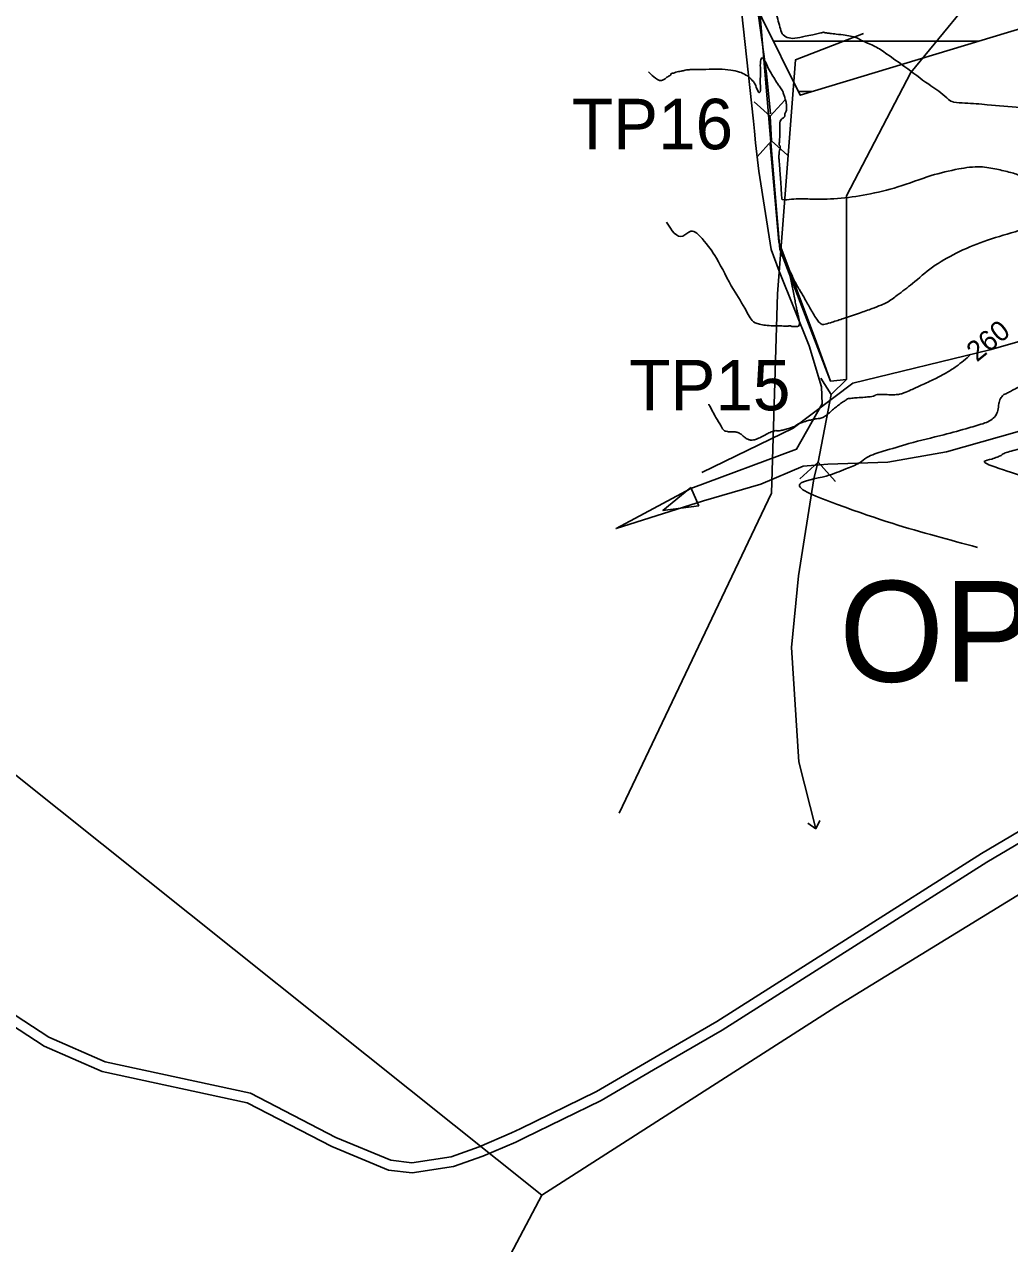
# Model space of a CAD drawing. Extents: x -478232 to -472707, y -1118753 to -1113967.
# Drawn here: x -476364.6 to -476169.2, y -1115916.9 to -1115675.1 of the extents above; entities that cross this region are included whole.
import ezdxf

# ---------------------------------------------------------------- set-up
doc = ezdxf.new("R2010")
doc.units = 0
for name, color, linetype in [('cesty', 7, 'Continuous'), ('DESQ_pomoc', 7, 'Continuous'), ('el vedeni _VN', 7, 'Continuous'), ('meliorace', 7, 'Continuous'), ('ObPÚ', 7, 'Continuous'), ('plyn_stl', 7, 'Continuous'), ('příkop', 7, 'Continuous'), ('silnice', 7, 'Continuous'), ('TP _navrh', 7, 'Continuous'), ('TP_stavajicí_mosty', 7, 'Continuous'), ('vodní plochy', 7, 'Continuous'), ('Vrstevnice_hlavni', 7, 'Continuous'), ('Vrstevnice_popis', 7, 'Continuous'), ('Vrstevnice_vedlejsi', 7, 'Continuous')]:
    doc.layers.add(name, color=color, linetype=linetype)

msp = doc.modelspace()

# ---------------------------------------------------------------- linework, layer by layer
at = {"layer": 'cesty'}
msp.add_line((-476230.782, -1115770.594), (-476232.376, -1115766.926), dxfattribs=at)
msp.add_lwpolyline([(-476232.376, -1115766.926), (-476237.951, -1115771.528), (-476230.782, -1115770.594)], dxfattribs=at)
at = {"layer": 'DESQ_pomoc'}
for points in [[(-476201.534, -1115745.526), (-476201.534, -1115733.375), (-476201.534, -1115709.114), (-476188.744, -1115684.672), (-476172.449, -1115664.757), (-476160.138, -1115645.565), (-476134.066, -1115608.631), (-476115.78, -1115589.982), (-476098.037, -1115567.894), (-476077.94, -1115547.978), (-476048.248, -1115512.854), (-476043.993, -1115447.585)], [(-476267.087, -1115462.209), (-476244.37, -1115506.43), (-476242.315, -1115514.072), (-476242.274, -1115519.975), (-476242.646, -1115529.053), (-476245.764, -1115545.902), (-476246.268, -1115555.752), (-476245.646, -1115566.754), (-476228.592, -1115621.781), (-476225.387, -1115633.24), (-476218.708, -1115672.632), (-476214.725, -1115719.706), (-476204.67, -1115745.863), (-476201.534, -1115745.526)]]:
    msp.add_lwpolyline(points, dxfattribs=at)
at = {"layer": 'el vedeni _VN'}
msp.add_lwpolyline([(-476246.598, -1115831.504), (-476216.386, -1115768.05), (-476215.19, -1115728.562), (-476211.67, -1115682.14), (-476198.145, -1115676.925)], dxfattribs=at)
at = {"layer": 'meliorace'}
for p, q in [((-476216.019, -1115678.417), (-476175.305, -1115678.417)), ((-476211.058, -1115688.417), (-476208.305, -1115688.417))]:
    msp.add_line(p, q, dxfattribs=at)
msp.add_lwpolyline([(-475930.536, -1115473.639), (-475966.096, -1115498.642), (-475977.78, -1115575.318), (-475994.29, -1115626.039), (-476095.89, -1115666.758), (-476110.114, -1115658.662), (-476210.698, -1115689.142), (-476225.938, -1115658.424), (-476218.572, -1115651.28), (-476221.366, -1115635.564), (-476230.256, -1115618.895), (-476240.416, -1115599.845), (-476255.656, -1115572.46), (-476259.466, -1115568.889), (-476264.546, -1115546.267), (-476300.106, -1115567.698), (-476326.776, -1115514.12)], dxfattribs=at)
at = {"layer": 'ObPÚ'}
msp.add_lwpolyline([(-476225.42, -1115644.37), (-476219.95, -1115694.26), (-476219.77, -1115696.28), (-476219.56, -1115698.57), (-476218.93, -1115704.24), (-476216.46, -1115719.75), (-476214.88, -1115724.06), (-476208.91, -1115738.82), (-476206.48, -1115747), (-476206.37, -1115750.33), (-476211.42, -1115759.32), (-476232.43, -1115767.11), (-476247.23, -1115775.1), (-476229.89, -1115769.61), (-476218.53, -1115766.28), (-476210.09, -1115762.68), (-476205.25, -1115762.34), (-476193.32, -1115761.9), (-476181.71, -1115759.89), (-476167.64, -1115755.89), (-476126.07, -1115741.56), (-476097.4, -1115735.87), (-476082.36, -1115734.08), (-476080.7, -1115733.86)], dxfattribs=at)
at = {"layer": 'plyn_stl'}
msp.add_lwpolyline([(-476230.25, -1115763.97), (-476212.09, -1115755.18), (-476200.29, -1115746.23), (-476173.09, -1115739.64), (-476150.98, -1115733.39)], dxfattribs=at)
at = {"layer": 'příkop'}
for q in [(-476209.19, -1115833.49), (-476206.807, -1115832.957)]:
    msp.add_line((-476207.63, -1115834.61), q, dxfattribs=at)
for points in [[(-476224.857, -1115633.023), (-476224.505, -1115634.082), (-476223.006, -1115644.102), (-476219.219, -1115671.509), (-476217.407, -1115684.861), (-476216.585, -1115692.813)], [(-476216.661, -1115698.872), (-476214.95, -1115718.2), (-476207.45, -1115738.16), (-476204.67, -1115745.863)], [(-476207.11, -1115761.74), (-476207.99, -1115765.23), (-476211.04, -1115784.48), (-476212.45, -1115798.65), (-476210.97, -1115821.36), (-476207.63, -1115834.61)]]:
    msp.add_lwpolyline(points, dxfattribs=at)
at = {"layer": 'silnice'}
for points in [[(-476261.922, -1115907.288), (-476203.622, -1115869.922), (-476022.083, -1115758.582), (-475811.314, -1115629.283), (-475771.826, -1115610.299), (-475706.185, -1115581.566), (-475629.775, -1115551.807), (-475577.467, -1115527.178), (-475544.647, -1115503.063), (-475523.184, -1115471.236), (-475482.102, -1115402.498), (-475367.21, -1115204.445), (-475326.334, -1115129.255), (-475275.418, -1115058.05)], [(-475903.982, -1117378.322), (-475889.519, -1117318.176), (-475888.389, -1117289.008), (-475895.395, -1117261.196), (-475916.638, -1117209.19), (-475969.886, -1117075.455), (-476021.05, -1116948.737), (-476052.923, -1116863.979), (-476081.44, -1116727.192), (-476114.99, -1116491.378), (-476128.411, -1116405.781), (-476137.637, -1116368.017), (-476162.8, -1116322.7), (-476200.543, -1116268.153), (-476239.965, -1116179.199), (-476260.934, -1116109.546), (-476288.613, -1116007.164), (-476289.451, -1115970.24), (-476274.354, -1115930.798), (-476261.922, -1115907.288), (-476366.595, -1115823.727)]]:
    msp.add_lwpolyline(points, dxfattribs=at)
at = {"layer": 'TP _navrh'}
msp.add_lwpolyline([(-476206.636, -1115745.227), (-476204.533, -1115748.511), (-476201.534, -1115745.526), (-476204.533, -1115748.511), (-476207.14, -1115761.941), (-476203.773, -1115765.701), (-476207.14, -1115761.941), (-476210.802, -1115765.219)], dxfattribs=at)
at = {"layer": 'TP_stavajicí_mosty'}
for p, q in [((-476219.849, -1115690.463), (-476216.667, -1115693.304)), ((-476213.769, -1115690.14), (-476216.633, -1115693.302)), ((-476216.667, -1115693.304), (-476216.388, -1115698.181)), ((-476216.633, -1115693.302), (-476216.394, -1115698.181)), ((-476216.388, -1115698.181), (-476219.225, -1115701.366)), ((-476216.394, -1115698.181), (-476213.236, -1115701.048))]:
    msp.add_line(p, q, dxfattribs=at)
at = {"layer": 'vodní plochy'}
for points in [[(-475779.213, -1115723.58), (-475781.955, -1115723.615), (-475790.416, -1115718.325), (-475794.426, -1115716.682), (-475798.584, -1115714.694), (-475810.721, -1115710.345), (-475841.882, -1115701.514), (-475880.38, -1115690.714), (-475893.822, -1115686.598), (-475898.085, -1115684.655), (-475904.925, -1115681.219), (-475916.412, -1115686.876), (-475958.026, -1115710.973), (-475986.66, -1115727.189), (-476011.342, -1115743.218), (-476037.238, -1115758.87), (-476062.612, -1115773.996), (-476091.04, -1115791.638), (-476123.208, -1115810.698), (-476141.742, -1115820.058), (-476174.712, -1115839.526), (-476227.25, -1115872.829), (-476240.81, -1115880.736)], [(-476265.408, -1115895.911), (-476250.185, -1115888.516), (-476239.802, -1115882.464), (-476226.21, -1115874.539), (-476173.668, -1115841.232), (-476140.782, -1115821.814), (-476122.246, -1115812.452), (-476090.002, -1115793.348), (-476061.572, -1115775.704), (-476036.208, -1115760.584), (-476010.28, -1115744.912), (-475985.622, -1115728.899)], [(-476375.634, -1115868.031), (-476360.7, -1115877.712), (-476349.186, -1115882.767), (-476320.432, -1115888.987), (-476303.631, -1115897.664), (-476292.397, -1115902.299), (-476287.698, -1115902.886), (-476279.459, -1115901.618), (-476273.652, -1115899.541), (-476267.142, -1115896.753), (-476265.408, -1115895.911)], [(-476240.81, -1115880.736), (-476251.127, -1115886.75), (-476266.282, -1115894.111), (-476267.974, -1115894.933), (-476274.384, -1115897.679), (-476279.953, -1115899.67), (-476287.726, -1115900.866), (-476291.883, -1115900.347), (-476302.789, -1115895.848), (-476319.75, -1115887.089), (-476348.566, -1115880.855), (-476359.748, -1115875.946), (-476374.7, -1115866.253)]]:
    msp.add_lwpolyline(points, dxfattribs=at)
at = {"layer": 'Vrstevnice_hlavni'}
msp.add_spline([(-476176.894, -1115740.594), (-476179.767, -1115742.933), (-476181.643, -1115744.14), (-476183.957, -1115745.384), (-476186.71, -1115746.665), (-476188.764, -1115747.593), (-476190.119, -1115748.168), (-476190.776, -1115748.389), (-476191.667, -1115748.519), (-476192.794, -1115748.555), (-476194.156, -1115748.499), (-476195.11, -1115748.495), (-476195.655, -1115748.543), (-476195.793, -1115748.644), (-476195.934, -1115748.73), (-476196.079, -1115748.799), (-476196.227, -1115748.853), (-476196.83, -1115748.929), (-476197.887, -1115749.028), (-476199.398, -1115749.15), (-476200.445, -1115749.235), (-476201.027, -1115749.285), (-476201.146, -1115749.299), (-476201.498, -1115749.498), (-476202.086, -1115749.883), (-476202.907, -1115750.454), (-476203.72, -1115751.074), (-476204.524, -1115751.744), (-476205.32, -1115752.464), (-476206.072, -1115752.964), (-476206.783, -1115753.244), (-476207.45, -1115753.304), (-476208.234, -1115753.449), (-476209.135, -1115753.679), (-476210.153, -1115753.993), (-476210.906, -1115754.266), (-476211.393, -1115754.497), (-476211.614, -1115754.688), (-476212.08, -1115754.912), (-476212.79, -1115755.169), (-476213.745, -1115755.459), (-476214.525, -1115755.637), (-476215.131, -1115755.704), (-476215.563, -1115755.658), (-476216.23, -1115755.836), (-476217.132, -1115756.235), (-476218.27, -1115756.858), (-476219.217, -1115757.28), (-476219.972, -1115757.503), (-476220.536, -1115757.525), (-476221.11, -1115757.362), (-476221.694, -1115757.012), (-476222.288, -1115756.476), (-476222.921, -1115756.117), (-476223.595, -1115755.935), (-476224.308, -1115755.93), (-476224.899, -1115755.886), (-476225.368, -1115755.803), (-476225.715, -1115755.681), (-476226.397, -1115754.772), (-476227.416, -1115753.074), (-476228.77, -1115750.587), (-476228.855, -1115750.439)], degree=3, dxfattribs=at)
at = {"layer": 'Vrstevnice_vedlejsi'}
for points in [[(-476227.986, -1115661.616), (-476227.829, -1115661.539), (-476227.091, -1115661.275), (-476225.773, -1115660.825), (-476223.875, -1115660.188), (-476222.549, -1115659.504), (-476221.794, -1115658.774), (-476221.612, -1115657.996), (-476221.483, -1115656.864), (-476221.409, -1115655.377), (-476221.39, -1115653.536), (-476221.219, -1115653), (-476220.898, -1115653.77), (-476220.425, -1115655.846), (-476220.044, -1115657.446), (-476219.755, -1115658.57), (-476219.557, -1115659.218), (-476219.119, -1115660.554), (-476218.442, -1115662.578), (-476217.526, -1115665.29), (-476216.754, -1115667.802), (-476216.127, -1115670.113), (-476215.643, -1115672.223), (-476215.172, -1115674.064), (-476214.714, -1115675.636), (-476214.269, -1115676.94), (-476213.291, -1115677.677), (-476211.778, -1115677.849), (-476209.732, -1115677.456), (-476208.193, -1115677.148), (-476207.162, -1115676.926), (-476206.639, -1115676.791), (-476206.278, -1115676.698), (-476206.079, -1115676.648), (-476206.043, -1115676.641), (-476205.991, -1115676.654), (-476205.924, -1115676.688), (-476205.841, -1115676.743), (-476205.736, -1115676.78), (-476205.61, -1115676.801), (-476205.463, -1115676.803), (-476204.774, -1115676.881), (-476203.544, -1115677.033), (-476201.772, -1115677.26), (-476200.409, -1115677.509), (-476199.454, -1115677.779), (-476198.909, -1115678.071), (-476198.137, -1115678.448), (-476197.139, -1115678.909), (-476195.914, -1115679.454), (-476193.519, -1115680.981), (-476189.955, -1115683.489), (-476185.22, -1115686.977), (-476182.029, -1115689.311), (-476180.382, -1115690.49), (-476180.278, -1115690.514), (-476178.021, -1115690.699), (-476173.61, -1115691.044), (-476167.046, -1115691.55), (-476162.398, -1115691.805), (-476159.667, -1115691.807), (-476158.853, -1115691.558), (-476157.344, -1115691.399), (-476155.139, -1115691.33), (-476152.239, -1115691.352), (-476149.334, -1115691.272), (-476146.424, -1115691.091), (-476143.508, -1115690.808), (-476141.245, -1115690.475), (-476139.633, -1115690.092), (-476138.674, -1115689.658), (-476137.503, -1115688.952), (-476136.121, -1115687.974), (-476134.526, -1115686.724), (-476132.977, -1115685.844), (-476131.471, -1115685.333), (-476130.01, -1115685.192), (-476128.96, -1115685.035), (-476128.321, -1115684.861), (-476128.094, -1115684.672), (-476127.864, -1115684.175), (-476127.633, -1115683.373), (-476127.4, -1115682.264), (-476127.318, -1115681.284), (-476127.387, -1115680.433), (-476127.607, -1115679.711), (-476127.563, -1115678.771), (-476127.254, -1115677.611), (-476126.681, -1115676.232), (-476126.164, -1115675.217), (-476125.703, -1115674.568), (-476125.297, -1115674.283), (-476124.853, -1115673.951), (-476124.37, -1115673.573), (-476123.849, -1115673.149), (-476123.344, -1115672.885), (-476122.855, -1115672.783)], [(-476214.705, -1115699.809), (-476214.847, -1115700.358), (-476214.912, -1115701.057), (-476214.903, -1115701.906), (-476214.818, -1115702.905), (-476214.719, -1115704.215), (-476214.606, -1115705.838), (-476214.478, -1115707.774), (-476214.392, -1115709.068), (-476214.348, -1115709.721), (-476214.346, -1115709.733), (-476214.343, -1115709.746), (-476214.339, -1115709.761), (-476214.334, -1115709.776), (-476214.317, -1115709.791), (-476214.289, -1115709.803), (-476214.248, -1115709.814), (-476212.408, -1115709.79), (-476208.77, -1115709.73), (-476203.333, -1115709.635), (-476197.514, -1115708.83), (-476191.311, -1115707.316), (-476184.727, -1115705.092), (-476179.266, -1115703.77), (-476174.929, -1115703.348), (-476171.716, -1115703.827), (-476168.969, -1115704.464), (-476166.688, -1115705.259), (-476164.873, -1115706.211), (-476163.512, -1115706.782), (-476162.605, -1115706.97), (-476162.152, -1115706.776), (-476161.648, -1115706.56), (-476161.093, -1115706.324), (-476160.486, -1115706.067), (-476159.458, -1115705.634), (-476158.008, -1115705.027), (-476156.136, -1115704.244), (-476154.791, -1115703.668), (-476153.971, -1115703.298), (-476153.678, -1115703.136), (-476153.325, -1115702.995), (-476152.911, -1115702.877), (-476152.437, -1115702.78), (-476150.571, -1115702.418), (-476147.312, -1115701.788), (-476142.66, -1115700.891), (-476139.378, -1115700.274), (-476137.467, -1115699.936), (-476136.925, -1115699.878), (-476135.481, -1115699.498), (-476133.134, -1115698.797), (-476129.885, -1115697.775), (-476127.11, -1115696.809), (-476124.809, -1115695.899), (-476122.982, -1115695.044), (-476121.665, -1115694.348), (-476120.859, -1115693.809), (-476120.563, -1115693.429), (-476119.861, -1115692.978), (-476118.754, -1115692.455), (-476117.243, -1115691.862), (-476116.18, -1115691.433), (-476115.567, -1115691.169), (-476115.403, -1115691.071), (-476115.251, -1115690.805), (-476115.11, -1115690.372), (-476114.981, -1115689.771), (-476114.845, -1115689.209), (-476114.701, -1115688.685), (-476114.551, -1115688.199), (-476114.534, -1115687.754), (-476114.649, -1115687.35), (-476114.896, -1115686.987), (-476115.156, -1115686.451), (-476115.427, -1115685.743), (-476115.711, -1115684.861), (-476115.94, -1115684.029), (-476116.112, -1115683.244), (-476116.23, -1115682.509), (-476116.314, -1115681.669), (-476116.366, -1115680.726), (-476116.385, -1115679.68), (-476116.408, -1115678.836), (-476116.436, -1115678.195), (-476116.467, -1115677.756), (-476116.475, -1115677.418), (-476116.458, -1115677.18), (-476116.417, -1115677.042), (-476116.258, -1115676.851), (-476115.978, -1115676.608), (-476115.58, -1115676.312), (-476115.294, -1115676.109), (-476115.121, -1115676.001), (-476115.062, -1115675.987), (-476115.001, -1115675.974), (-476114.939, -1115675.963)], [(-476240.812, -1115684.536), (-476239.76, -1115685.48), (-476238.244, -1115686.253), (-476237.283, -1115685.695), (-476236.647, -1115685.288), (-476236.336, -1115685.033), (-476236.35, -1115684.93), (-476236.023, -1115684.783), (-476235.356, -1115684.593), (-476234.349, -1115684.36), (-476233.54, -1115684.196), (-476232.929, -1115684.101), (-476232.515, -1115684.076), (-476231.341, -1115684.048), (-476229.408, -1115684.017), (-476226.713, -1115683.982), (-476224.491, -1115684.157), (-476222.741, -1115684.543), (-476221.462, -1115685.14), (-476220.435, -1115685.953), (-476219.66, -1115686.984), (-476219.136, -1115688.231), (-476218.787, -1115688.633), (-476218.613, -1115688.189), (-476218.615, -1115686.9), (-476218.606, -1115685.5), (-476218.589, -1115683.99), (-476218.561, -1115682.368), (-476218.32, -1115681.739), (-476217.866, -1115682.1), (-476217.197, -1115683.454), (-476216.497, -1115684.742), (-476215.764, -1115685.965), (-476214.999, -1115687.123), (-476214.483, -1115687.903), (-476214.214, -1115688.305), (-476214.195, -1115688.33), (-476214.175, -1115688.358), (-476214.157, -1115688.392), (-476214.14, -1115688.431), (-476214.063, -1115688.657), (-476213.927, -1115689.072), (-476213.732, -1115689.675), (-476213.592, -1115690.144), (-476213.509, -1115690.477), (-476213.481, -1115690.676), (-476213.453, -1115690.933), (-476213.424, -1115691.247), (-476213.394, -1115691.619), (-476213.42, -1115691.963), (-476213.5, -1115692.279), (-476213.636, -1115692.567), (-476213.722, -1115692.791), (-476213.757, -1115692.949), (-476213.742, -1115693.043), (-476213.743, -1115693.145), (-476213.758, -1115693.254), (-476213.788, -1115693.371), (-476213.912, -1115693.517), (-476214.131, -1115693.692), (-476214.444, -1115693.896), (-476214.649, -1115694.308), (-476214.745, -1115694.929), (-476214.732, -1115695.758), (-476214.736, -1115696.516), (-476214.756, -1115697.202), (-476214.793, -1115697.816), (-476214.831, -1115698.295), (-476214.87, -1115698.637), (-476214.91, -1115698.844), (-476214.894, -1115699.005), (-476214.822, -1115699.121), (-476214.693, -1115699.19), (-476214.654, -1115699.42), (-476214.705, -1115699.809)], [(-476237.229, -1115714.298), (-476234.006, -1115717.074), (-476232.377, -1115716.127), (-476230.156, -1115717.581), (-476227.341, -1115721.436), (-476223.934, -1115727.692), (-476221.371, -1115731.964), (-476219.654, -1115734.254), (-476218.781, -1115734.56), (-476217.601, -1115734.769), (-476216.113, -1115734.879), (-476214.319, -1115734.891), (-476213.105, -1115734.915), (-476212.472, -1115734.95), (-476212.42, -1115734.997), (-476212.201, -1115735.021), (-476211.814, -1115735.022), (-476211.259, -1115735), (-476210.928, -1115734.777), (-476210.821, -1115734.355), (-476210.936, -1115733.732), (-476211.074, -1115733.044), (-476211.234, -1115732.291), (-476211.416, -1115731.472), (-476211.617, -1115730.477), (-476211.838, -1115729.304), (-476212.079, -1115727.955), (-476212.336, -1115726.663), (-476212.608, -1115725.428), (-476212.896, -1115724.249), (-476212.916, -1115723.836), (-476212.669, -1115724.189), (-476212.154, -1115725.306), (-476211.698, -1115726.234), (-476211.301, -1115726.972), (-476210.963, -1115727.521), (-476210.534, -1115728.249), (-476210.012, -1115729.155), (-476209.398, -1115730.24), (-476208.764, -1115731.339), (-476208.109, -1115732.452), (-476207.433, -1115733.578), (-476206.817, -1115734.306), (-476206.263, -1115734.634), (-476205.769, -1115734.564), (-476204.382, -1115734.16), (-476202.1, -1115733.421), (-476198.924, -1115732.349), (-476196.436, -1115731.462), (-476194.637, -1115730.76), (-476193.526, -1115730.243), (-476191.464, -1115728.823), (-476188.451, -1115726.499), (-476184.486, -1115723.271), (-476179.77, -1115720.485), (-476174.302, -1115718.14), (-476168.083, -1115716.236), (-476163.813, -1115714.804), (-476161.491, -1115713.844)], [(-476083.35, -1115714.516), (-476083.737, -1115714.901), (-476084.454, -1115715.569), (-476085.504, -1115716.521), (-476086.885, -1115717.757), (-476088.732, -1115719.111), (-476091.045, -1115720.582), (-476093.824, -1115722.172), (-476095.763, -1115723.267), (-476096.863, -1115723.867), (-476097.123, -1115723.972), (-476097.881, -1115724.281), (-476099.136, -1115724.793), (-476100.888, -1115725.508), (-476102.376, -1115726.082), (-476103.6, -1115726.515), (-476104.56, -1115726.807), (-476105.403, -1115727.084), (-476106.13, -1115727.348), (-476106.741, -1115727.598), (-476107.467, -1115727.778), (-476108.31, -1115727.89), (-476109.268, -1115727.932), (-476110.126, -1115728.045), (-476110.885, -1115728.229), (-476111.543, -1115728.483), (-476112.224, -1115728.948), (-476112.928, -1115729.622), (-476113.654, -1115730.505), (-476114.326, -1115731.307), (-476114.944, -1115732.026), (-476115.507, -1115732.663), (-476116.047, -1115733.159), (-476116.564, -1115733.514), (-476117.059, -1115733.727), (-476117.702, -1115734.107), (-476118.495, -1115734.656), (-476119.436, -1115735.373), (-476120.327, -1115735.997), (-476121.168, -1115736.526), (-476121.958, -1115736.962), (-476122.823, -1115737.486), (-476123.763, -1115738.099), (-476124.778, -1115738.8), (-476125.735, -1115739.292), (-476126.632, -1115739.573), (-476127.47, -1115739.645), (-476128.75, -1115740.015), (-476130.471, -1115740.684), (-476132.634, -1115741.652), (-476134.795, -1115742.625), (-476136.953, -1115743.605), (-476139.108, -1115744.59), (-476141.994, -1115745.917), (-476145.611, -1115747.588), (-476149.959, -1115749.601), (-476153.119, -1115751.123), (-476155.09, -1115752.155), (-476155.874, -1115752.695), (-476156.618, -1115753.168), (-476157.324, -1115753.573), (-476157.99, -1115753.91), (-476158.626, -1115754.248), (-476159.232, -1115754.587), (-476159.807, -1115754.927), (-476160.352, -1115755.268), (-476160.868, -1115755.611), (-476161.354, -1115755.954), (-476161.819, -1115756.252), (-476162.263, -1115756.505), (-476162.685, -1115756.713), (-476162.982, -1115756.978), (-476163.154, -1115757.298), (-476163.201, -1115757.674), (-476163.347, -1115757.978), (-476163.592, -1115758.209), (-476163.936, -1115758.368), (-476164.807, -1115758.637), (-476166.206, -1115759.017), (-476168.132, -1115759.509), (-476169.551, -1115759.931), (-476170.462, -1115760.285), (-476170.866, -1115760.569), (-476171.619, -1115760.908), (-476172.719, -1115761.302), (-476174.168, -1115761.75), (-476172.131, -1115762.861), (-476166.608, -1115764.635), (-476157.598, -1115767.072), (-476148.181, -1115770.218)], [(-476116.137, -1115720.383), (-476116.92, -1115720.991), (-476117.571, -1115721.526), (-476118.088, -1115721.988), (-476118.471, -1115722.375), (-476118.885, -1115722.712), (-476119.329, -1115722.998), (-476119.804, -1115723.234), (-476121.396, -1115723.667), (-476124.106, -1115724.298), (-476127.934, -1115725.127), (-476130.568, -1115725.531), (-476132.01, -1115725.511), (-476132.259, -1115725.067), (-476132.481, -1115724.927), (-476132.675, -1115725.092), (-476132.843, -1115725.561), (-476134.648, -1115726.435), (-476138.091, -1115727.714), (-476143.171, -1115729.398), (-476146.868, -1115730.978), (-476149.181, -1115732.452), (-476150.109, -1115733.822), (-476150.952, -1115734.963), (-476151.707, -1115735.875), (-476152.376, -1115736.559), (-476153.25, -1115737.248), (-476154.331, -1115737.944), (-476155.618, -1115738.646), (-476156.933, -1115739.422), (-476158.278, -1115740.271), (-476159.653, -1115741.193), (-476161.15, -1115742.278), (-476162.772, -1115743.528), (-476164.517, -1115744.941), (-476165.993, -1115746.061), (-476167.2, -1115746.887), (-476168.139, -1115747.419), (-476168.993, -1115747.887), (-476169.764, -1115748.29), (-476170.45, -1115748.628), (-476170.964, -1115749.303), (-476171.306, -1115750.315), (-476171.474, -1115751.663), (-476171.997, -1115752.752), (-476172.874, -1115753.581), (-476174.105, -1115754.149), (-476177.228, -1115755.115), (-476182.241, -1115756.479), (-476189.145, -1115758.239), (-476194.231, -1115759.753), (-476197.497, -1115761.02), (-476198.945, -1115762.04), (-476201.641, -1115763.256), (-476205.586, -1115764.667), (-476210.779, -1115766.273), (-476203.477, -1115770.255), (-476183.682, -1115776.613), (-476175.538, -1115778.82)]]:
    msp.add_spline(points, degree=3, dxfattribs=at)

# ---------------------------------------------------------------- texts
at = {"layer": 'příkop'}
msp.add_text('OP2b', height=20, rotation=359.99999, dxfattribs=at).set_placement((-476202.98, -1115805.469))
at = {"layer": 'TP _navrh'}
msp.add_text('TP15', height=10, rotation=359.99999, dxfattribs=at).set_placement((-476244.611, -1115751.635))
at = {"layer": 'TP_stavajicí_mosty'}
msp.add_text('TP16', height=10, rotation=359.99999, dxfattribs=at).set_placement((-476255.987, -1115699.857))
at = {"layer": 'Vrstevnice_popis'}
msp.add_text(' 260 ', height=4, rotation=39.144, dxfattribs=at).set_placement((-476176.812, -1115743.106))

doc.saveas('drawing.dxf')
